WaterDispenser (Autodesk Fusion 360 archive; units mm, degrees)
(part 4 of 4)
sketch "Sketch16" plane through (0, -6, 0) normal (0, 1, 0) x axis (-1, 0, 0)
  line L1 (45, -40) -> (-45, -40)
  line L2 (45, 50) -> (45, -40)
  line L3 (-45, 50) -> (45, 50)
  line L4 (-45, -40) -> (-45, 50)
  line L5 (-15.5, -15.5) -> (15.5, -15.5)
  line L6 (-15.5, 15.5) -> (-15.5, -15.5)
  line L7 (15.5, 15.5) -> (-15.5, 15.5)
  line L8 (15.5, -15.5) -> (15.5, 15.5)
  line L9 (-15.5, 15.5) -> (15.5, -15.5)
  line L10 (15.5, 15.5) -> (-15.5, -15.5)
  circle C1 centre (-39, 0) radius 3.5
  circle C2 centre (39, 39) radius 3.5
  circle C3 centre (-39, -34) radius 3.5
  circle C4 centre (-39, 39) radius 3.5
  circle C5 centre (39, 0) radius 3.5
  circle C6 centre (39, -33.75) radius 3.5
  circle C7 centre (0, 39) radius 3.5
  circle C8 centre (0, 0) radius 11
  circle C9 centre (15.5, -15.5) radius 1.5
  circle C10 centre (15.5, 15.5) radius 1.5
  circle C11 centre (-15.5, -15.5) radius 1.5
  circle C12 centre (-15.5, 15.5) radius 1.5
  circle C13 centre (15.5, -15.5) radius 3.5
  circle C14 centre (-15.5, -15.5) radius 3.5
  circle C15 centre (-15.5, 15.5) radius 3.5
  circle C16 centre (15.5, 15.5) radius 3.5
  point P18 (0, 0)
  point P9 (0, 0)
  point P14 (15.5, -15.5)
  point P19 (15.5, -15.5)
  point P17 (15.5, 15.5)
  point P20 (15.5, 15.5)
  point P15 (-15.5, -15.5)
  point P21 (-15.5, -15.5)
  point P16 (-15.5, 15.5)
  point P22 (-15.5, 15.5)
  point P23 (15.5, -15.5)
  point P24 (-15.5, -15.5)
  point P25 (-15.5, 15.5)
  point P26 (15.5, 15.5)
  perpendicular L5 L6
  parallel L5 L7
  parallel L6 L8
  horizontal L5
  coincident L9 P18
  coincident L10 P18
  coincident P9 P18
  coincident P14 P19
  coincident P17 P20
  coincident P15 P21
  coincident P16 P22
  coincident P14 P23
  coincident P15 P24
  coincident P16 P25
  coincident P17 P26
  dimension "d139" distance P16 P17 = 31 (= "DistanceScrewMotor")
  dimension "d140" distance L5 L7 = 31 (= "DistanceScrewMotor")
  dimension "d142" diameter C9 = 3 (= "ScrewMotorDiameter")
  dimension "d143" diameter C10 = 3 (= "ScrewMotorDiameter")
  dimension "d144" diameter C11 = 3 (= "ScrewMotorDiameter")
  dimension "d145" diameter C12 = 3 (= "ScrewMotorDiameter")
  dimension "d150" diameter C13 = 7 (= "ScrewMotorHeadDiameter")
  dimension "d151" diameter C14 = 7 (= "ScrewMotorHeadDiameter")
  dimension "d152" diameter C15 = 7 (= "ScrewMotorHeadDiameter")
  dimension "d153" diameter C16 = 7 (= "ScrewMotorHeadDiameter")
extrude "Extrude7" cut sketch "Sketch16" profile of C9 C10 C11 C12 to an object
extrude "Extrude8" cut sketch "Sketch16" profile of C9 C10 C11 C12 C13 C14 C15 C16 no distance stored
extrude "Extrude9" add of existing geometry blind 4.5
extrude "Extrude8" cut of existing geometry blind -0.5
extrude "Extrude9" cut of existing geometry blind -0.5
extrude "Extrude10" add of existing geometry blind 4
extrude "Extrude11" add of existing geometry blind 4
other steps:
extrude "Extrude3" cut sketch "Sketch6" profile of C3 C4 C5 to an object Side2Offset 0
sweep "Sweep1" sketch "Sketch10" TwistAngle 0 TaperAngle 0
create_component "CreateComponent1"
create_component "CreateComponent2"
create_component "CreateComponent3"
create_component "CreateComponent4"
extrude "Extrude2" cut sketch "Sketch2" profile of C2 C3 C4 C5 C6 C7 C8 to an object Side2Offset 0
